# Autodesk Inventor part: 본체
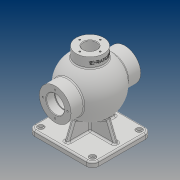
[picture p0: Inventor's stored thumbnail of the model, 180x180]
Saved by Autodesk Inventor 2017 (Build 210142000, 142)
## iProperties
Part Number: 본체
Material: 일반
Document SubType Name: Modeling
Designer: 13
Density: 1 g/cm^3
Appearance: 기본값
Author: 13
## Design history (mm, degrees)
sketch "스케치1"
  geometry: L1 (-68, 0)-(68, 0); L2 (39.278, 17.5)-(68, 17.5); L3 (-68, 17.5)-(-68, 31); L4 (-68, 31)-(-42.988, 31); L5 (68, 17.5)-(68, 31); L6 (68, 31)-(42.988, 31); L7 (-39.278, 17.5)-(-50.25, 17.5); L8 (-50.25, 17.5)-(-50.25, 18.5); L9 (-50.25, 18.5)-(-52, 18.5); L10 (-52, 18.5)-(-52, 17.5); L11 (-52, 17.5)-(-68, 17.5); A1 r 43 centre (0, 0) between (39.278, 17.5) and (-39.278, 17.5); A2 r 53 centre (0, 0) between (42.988, 31) and (-42.988, 31); 2 further points
  constraints: 22 end point, 7 horizontal, 4 point on circle, 4 vertical, 3 coincident, 3 point on line, 2 centre point, 1 midpoint
  dimensions: "d0" = 136 distance of L1.start L1.end; "d1" = 43 radius of A1; "d2" = 53 radius of A2; "d4" = 62 diameter of L4 L1; "d5" = 35 diameter of L2 L1; "d6" = 62 diameter of L6 L1; "d92" = 35 diameter of L11 L1; "d93" = 37 diameter of L9 L1; "d94" = 1.75 distance between parallel lines of L10 L8; "d95" = 16 distance between parallel lines of L3 L10
revolve "회전1" sketch "스케치1" stored, may be unused: angle "d7" = 90 deg
node "작업 평면1"
sketch "스케치4"
  geometry: L1 (-62.5, 57.5)-(62.5, 57.5); L2 (62.5, 57.5)-(62.5, -57.5); L3 (62.5, -57.5)-(-62.5, -57.5); L4 (-62.5, -57.5)-(-62.5, 57.5); L5 (-62.5, 57.5)-(62.5, -57.5); L6 (62.5, 57.5)-(-62.5, -57.5); 1 further point
  constraints: 12 end point, 2 midpoint, 2 parallel, 1 horizontal, 1 perpendicular
  dimensions: "d31" = 125 distance of L1.start L1.end; "d32" = 115 distance of L1.end L2.end
extrude "돌출1" join sketch "스케치4" distance "d33" = 10; taper "d34" = 0 deg
fillet "모깎기1" dims "d53" = 12
hole "구멍3" diameter "d56" = 8; stored, may be unused: countersink angle "d60" = 90 deg, drill point angle "d62" = 0 deg; dims "d54" = 10, "d55" = 10, "d57" = 8, "d58" = 12, "d59" = 3, "d61" = 10
node "작업 평면2"
sketch "스케치9"
  geometry: C1 r 27 at (0, 0); 1 further point
  constraints: 1 centre point, 1 coincident
  dimensions: "d70" = 54 diameter of C1
extrude "돌출5" join sketch "스케치9" stored distance "d71" = 8; taper "d72" = 0 deg
sketch "스케치11"
  geometry: C1 r 13 at (0, 0); 1 further point
  constraints: 1 centre point, 1 coincident
  dimensions: "d73" = 26 diameter of C1
extrude "돌출6" cut sketch "스케치11" distance "d74" = 40; taper "d75" = 0 deg
sketch "스케치12"
  geometry: 2 further points
  constraints: 1 vertical alignment
  dimensions: "d76" = 20 distance of point (0, 0) point (0, 20)
hole "구멍4" sketch "스케치12" at (0, 20) diameter "d77" = 3.242; stored, may be unused: countersink angle "d81" = 90 deg, drill point angle "d83" = 118 deg; dims "d78" = 9, "d79" = 12, "d80" = 3, "d82" = 11
fillet "모깎기2" dims "d87" = 3
fillet "모깎기3" dims "d88" = 3
fillet "모깎기4" dims "d89" = 3
sketch "스케치13"
  geometry: 2 further points
  constraints: 1 vertical alignment
  dimensions: "d96" = 24 distance of point (0, 0) point (0, 24)
hole "구멍5" sketch "스케치13" at (0, 24) diameter "d97" = 3.242; stored, may be unused: countersink angle "d101" = 90 deg, drill point angle "d103" = 118 deg; dims "d98" = 16, "d99" = 12, "d100" = 3, "d102" = 19
sketch "스케치14"
  geometry: 2 further points
  constraints: 1 vertical alignment
  dimensions: "d107" = 22.5 distance of point (0, 0) point (0, -22.5)
hole "구멍6" sketch "스케치14" at (0, -22.5) diameter "d108" = 3.242; stored, may be unused: countersink angle "d112" = 90 deg, drill point angle "d114" = 118 deg; dims "d109" = 12, "d110" = 12, "d111" = 3, "d113" = 15
chamfer "모따기1" distance "d118" = 1; stored, may be unused: second distance "d119" = 2, angle "d120" = 45 deg
sketch "스케치29"
  geometry: L1 (52.5, -75)-(35.597, -33.164); L2 (62.5, -85)-(62.5, -78) reference; L3 (50.5, -75)-(-50.5, -75) reference; L4 (52.5, -75)-(0, -75); L5 (0, -75)-(0, -48.652); A1 r 48.652 centre (0, 0) between (0, -48.652) and (35.597, -33.164); 1 further point
  constraints: 6 end point, 2 point on circle, 1 centre point, 1 coincident, 1 midpoint, 1 point on line, 1 vertical
  dimensions: "d158" = 10 distance from line of L2 L1.start; "d159" = 22 deg angle of L2 L1; "d161" = 97.30374 diameter of A1
extrude "돌출9" join sketch "스케치29" stored distance "d162" = 8; taper "d163" = 0 deg
sketch "스케치30"
  geometry: L1 (-45.5, -75)-(45.5, -75) reference; L2 (-32.761, -38.519)-(-47.5, -75); L3 (-57.5, -85)-(-57.5, -78) reference; L4 (-47.5, -75)-(0, -75); L5 (0, -75)-(0, -50.566); A1 r 50.566 centre (0, 0) between (-32.761, -38.519) and (0, -50.566); 1 further point
  constraints: 6 end point, 2 point on circle, 1 centre point, 1 coincident, 1 midpoint, 1 point on line, 1 vertical
  dimensions: "d164" = 10 distance from line of L3 L2.end; "d165" = 22 deg angle of L3 L2; "d166" = 101.13283 diameter of A1
extrude "돌출10" join sketch "스케치30" stored distance "d167" = 8; taper "d168" = 0 deg
fillet "모깎기8" dims "d169" = 3
fillet "모깎기9" dims "d170" = 3
node "작업 평면4"
sketch "스케치32"
  geometry: L1 (-27, 65)-(-27, 47.286) reference; L2 (27, 65)-(-27, 65) reference; 2 further points
  constraints: 1 other
  dimensions: "d172" = 27 distance from line of L1 point (0, 55); "d173" = 10 distance from line of L2 point (0, 55)
feature "엠보싱1" sketch "스케치32" dims "d0" = 136, "d1" = 43, "d2" = 53, "d4" = 62, "d5" = 35, "d6" = 62, "d92" = 35, "d93" = 37, "d94" = 1.75, "d95" = 16, "d174" = 0.5, "d175" = 0
node "솔리드1"
pattern_linear "직사각형 패턴1" dims "d65" = 101, "d68" = 91
pattern_circular "원형 패턴3" dims angle "d85" = 360 deg
pattern_circular "원형 패턴4" dims angle "d105" = 360 deg
pattern_circular "원형 패턴5" dims angle "d116" = 360 deg
mirror "미러3"
mirror "미러4"
other parameters: "d30" = -85, "d171" = 65
